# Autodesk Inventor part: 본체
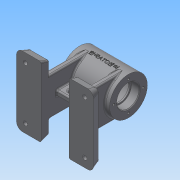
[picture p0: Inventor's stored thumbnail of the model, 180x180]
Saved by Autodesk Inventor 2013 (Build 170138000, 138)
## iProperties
Created: 2016-07
Part Number: 본체
Material: 일반
Document SubType Name: Modeling
Designer: Administrator
Density: 1 g/cm^3
Author: Administrator
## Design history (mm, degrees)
sketch "스케치1"
  geometry: C1 r 27 at (0, 0); 1 further point
  constraints: 1 centre point, 1 coincident
  dimensions: "d0" = 54 diameter of C1
extrude "돌출1" new body sketch "스케치1" distance "d1" = 35; taper "d2" = 0 deg
hole "구멍1" diameter "d5" = 28; stored, may be unused: countersink angle "d9" = 90 deg, drill point angle "d11" = 118 deg; dims "d3" = 10, "d4" = 10, "d6" = 6, "d7" = 32, "d8" = 12, "d10" = 8
sketch "스케치2"
  geometry: C1 r 14 at (0, 0) reference; C2 r 27 at (0, 0) reference; C3 r 22 at (0, 0)
  constraints: 1 centre point, 1 coincident
  dimensions: "d12" = 44 diameter of C3
extrude "돌출2" cut sketch "스케치2" distance "d13" = 21; taper "d14" = 0 deg
node "작업 평면1"
sketch "스케치5"
  geometry: L1 (-55, 50)-(-20, 50); L2 (-20, 50)-(-20, -50); L3 (-20, -50)-(-55, -50); L4 (-55, -50)-(-55, 50); 2 further points
  constraints: 8 end point, 2 parallel, 1 horizontal, 1 horizontal alignment, 1 midpoint, 1 perpendicular
  dimensions: "d16" = 100 distance of L3.end L1.start; "d18" = 35 distance of L1.start L1.end; "d19" = 55 distance from line of point (0, 0) L4
extrude "돌출3" join sketch "스케치5" distance "d20" = 12; taper "d21" = 0 deg
sketch "스케치6"
  geometry: L1 (20, 50)-(20, -50) reference; L2 (20, -27)-(28, -27); L3 (28, -27)-(28, 27); L4 (28, 27)-(20, 27); L5 (20, 27)-(20, -27); 5 further points
  constraints: 8 end point, 2 midpoint, 2 parallel, 1 coincident, 1 collinear, 1 horizontal, 1 perpendicular
  dimensions: "d31" = 54 distance of L2.end L3.end; "d33" = 8 distance of L3.end L4.end
extrude "돌출4" join sketch "스케치6" stored distance "d34" = 12; taper "d35" = 0 deg
sketch "스케치7"
  geometry: C1 r 16 at (0, 0) reference; 1 further point
  constraints: 1 vertical alignment
  dimensions: "d36" = 21 distance of C1.centre point (0, 21)
hole "구멍2" sketch "스케치7" at (0, 21) diameter "d37" = 3.242; stored, may be unused: countersink angle "d41" = 90 deg, drill point angle "d43" = 118 deg; dims "d38" = 8, "d39" = 32, "d40" = 12, "d42" = 10
chamfer "모따기4" distance "d47" = 1; stored, may be unused: second distance "d48" = 2, angle "d49" = 20 deg
chamfer "모따기5" distance "d61" = 12; stored, may be unused: second distance "d62" = 2, angle "d63" = 20 deg
chamfer "모따기6" distance "d64" = 12; stored, may be unused: second distance "d65" = 2, angle "d66" = 20 deg
chamfer "모따기7" distance "d67" = 12; stored, may be unused: second distance "d68" = 2, angle "d69" = 20 deg
fillet "모깎기2" dims "d70" = 5, "d71" = 10
fillet "모깎기3" dims "d72" = 10, "d73" = 5
fillet "모깎기4" dims "d74" = 2
node "작업 평면2"
sketch "스케치10"
  geometry: L1 (-35, 27)-(-35, -27) reference; L2 (35, 27)-(35, -27) reference; C1 r 5 at (13, 0); 1 further point
  constraints: 1 centre point, 1 horizontal alignment
  dimensions: "d76" = 10 diameter of C1; "d138" = 22 distance from line of L2 C1.centre
extrude "돌출5" join sketch "스케치10" stored distance "d79" = 12; taper "d80" = 0 deg
hole "구멍4" diameter "d83" = 5.188; stored, may be unused: countersink angle "d87" = 90 deg, drill point angle "d89" = 0 deg; dims "d81" = 10, "d82" = 10, "d84" = 20, "d85" = 10, "d86" = 4, "d88" = 20
sketch "스케치11"
  geometry: L1 (-20, -58)-(-20, 0) reference; L2 (-35, -27)-(35, -27) reference; L3 (20, -58)-(20, 0) reference; L4 (-20, -48)-(20, -48); 1 further point
  constraints: 2 end point, 2 point on line, 1 perpendicular
  dimensions: "d90" = 21 distance between parallel lines of L2 L4
feature "리브1" sketch "스케치11" dims "d91" = 1, "d92" = 8, "d93" = 0, "d94" = 0, "d95" = 1, "d96" = 1
sketch "스케치12"
  geometry: L1 (12, 13.5)-(28, 13.5); L2 (28, 6.5)-(12, 6.5); L3 (40, -22)-(66.555, -22) reference; A1 r 3.5 centre (12, 10) between (12, 13.5) and (12, 6.5); A2 r 3.5 centre (28, 10) between (28, 6.5) and (28, 13.5); 2 further points
  constraints: 4 end point, 4 point on circle, 4 tangent, 2 centre point, 1 horizontal, 1 midpoint, 1 parallel, 1 vertical alignment
  dimensions: "d97" = 23 dimension on A2 A1; "d100" = 3.5 radius of A2; "d101" = 32 distance from line of L3 A2.centre
extrude "돌출6" cut sketch "스케치12" stored distance "d102" = 0; taper "d103" = 0 deg
sketch "스케치13"
  geometry: L1 (0, 0)-(30, 0); L2 (0, 0)-(-25.441, -15.898); L3 (0, 0)-(30, 0)
  constraints: 6 end point, 2 horizontal, 1 equal length
  dimensions: "d106" = 30 distance of L1.start L2.end; "d107" = 212 deg dimension on L3 L2
node "작업 평면3"
sketch "스케치14"
  geometry: C1 r 6 at (0, 0); 1 further point
  constraints: 1 centre point, 1 coincident
  dimensions: "d108" = 12 diameter of C1
extrude "돌출7" join sketch "스케치14" stored distance "d109" = 12; taper "d110" = 0 deg
hole "구멍5" diameter "d113" = 5.188; stored, may be unused: countersink angle "d117" = 90 deg, drill point angle "d119" = 118 deg; dims "d111" = 10, "d112" = 10, "d114" = 15, "d115" = 10, "d116" = 4, "d118" = 15
fillet "모깎기5" dims "d120" = 2
fillet "모깎기6" dims "d121" = 0.3
fillet "모깎기7" dims "d122" = 3
fillet "모깎기8" dims "d123" = 2
node "작업 평면4"
sketch "스케치16"
  geometry: L1 (-35, -27)-(-35, 27) reference; L2 (-35, 27)-(35, 27) reference; 2 further points
  constraints: 1 other
  dimensions: "d125" = 35 distance from line of L1 point (0, 0); "d126" = 27 distance from line of point (0, 0) L2
feature "엠보싱1" sketch "스케치16" dims "d0" = 54, "d16" = 100, "d18" = 35, "d19" = 55, "d127" = 0.5, "d128" = 0
sketch "스케치17"
  geometry: L1 (22, 50)-(46.555, 50) reference; L2 (55, 41.555)-(55, -41.555) reference; 2 further points
  dimensions: "d129" = 12.5 distance from line of L1 point (42.5, 37.5); "d130" = 12.5 distance from line of L2 point (42.5, 37.5)
hole "구멍6" sketch "스케치17" at (42.5, 37.5) diameter "d131" = 6; stored, may be unused: countersink angle "d135" = 90 deg, drill point angle "d137" = 0 deg; dims "d132" = 15, "d133" = 10, "d134" = 4, "d136" = 15
node "솔리드1"
pattern_circular "원형 패턴1" dims angle "d45" = 360 deg
mirror "대칭2"
mirror "대칭3"
mirror "대칭4"
other parameters: "d124" = 27
